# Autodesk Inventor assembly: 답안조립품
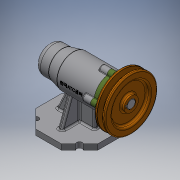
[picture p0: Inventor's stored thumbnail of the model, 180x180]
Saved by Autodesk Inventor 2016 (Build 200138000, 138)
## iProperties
Created: 2019-12
Part Number: 답안조립품
Document SubType Name: Assembly
Designer: MIRAE
Author: MIRAE
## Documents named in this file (12)
- C:\Users\MIRAE\Desktop\491204V1051\답안조립품.iam
- C:\Users\MIRAE\Desktop\491204V1051\본체.ipt
- C:\Users\MIRAE\Desktop\491204V1051\축.ipt
- C:\Users\MIRAE\Desktop\491204V1051\키 5 x 5 x 16.ipt
- C:\Users\MIRAE\Desktop\491204V1051\V벨트풀리.ipt
- C:\Users\MIRAE\Desktop\491204V1051\멈춤나사 M3.ipt
- C:\Users\MIRAE\Desktop\491204V1051\커버.ipt
- C:\Users\MIRAE\Desktop\491204V1051\볼트 M4.ipt
- C:\Users\MIRAE\Desktop\491204V1051\오일 실.ipt
- C:\Users\MIRAE\Desktop\491204V1051\베어링 6004.ipt
- C:\Users\MIRAE\Desktop\491204V1051\어댑터슬리브.ipt
- C:\Users\MIRAE\Desktop\491204V1051\베어링 51202.ipt
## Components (1 placed, 1 different names)
1. V벨트풀리:1
